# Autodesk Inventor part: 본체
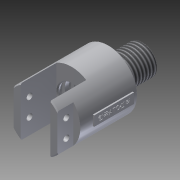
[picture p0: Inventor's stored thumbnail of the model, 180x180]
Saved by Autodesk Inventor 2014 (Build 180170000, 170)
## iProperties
Created: 2019-02
Part Number: 본체
Material: 알루미늄 6061
Document SubType Name: Modeling
Designer: OA55
Density: 2.71 g/cm^3
Appearance: 알루미늄 - 평지
Mass: 347.887 g
Surface Area: 290.046 cm^2
Volume: 128.372 cm^3
Author: OA55
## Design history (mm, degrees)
sketch "스케치1"
  geometry: C1 r 29 at (0, 0); 1 further point
  constraints: 1 centre point, 1 coincident
  dimensions: "d0" = 58 diameter of C1
extrude "돌출1" new body sketch "스케치1" stored distance "d1" = 74; taper "d2" = 0 deg
sketch "스케치2"
  geometry: L1 (29, -37)-(-29, -37) reference; L2 (-29, -37)-(-29, 37) reference; L3 (-29, 37)-(29, 37) reference; L4 (29, 37)-(29, -37) reference; L5 (15, 37)-(-15, 37); L6 (-15, 37)-(-15, 1); L7 (-15, 1)-(15, 1); L8 (15, 1)-(15, 37); L9 (22, 21)-(22, 37); L10 (0, 37)-(0, 0); L11 (22, 21)-(31.08, 21); L12 (31.08, 21)-(31.08, 37); L13 (31.08, 37)-(22, 37); L14 (-22, 21)-(-31.08, 21); L15 (-31.08, 21)-(-31.08, 37); L16 (-31.08, 37)-(-22, 37); L17 (-22, 21)-(-22, 37)
  constraints: 26 end point, 4 symmetric about line, 3 parallel, 2 perpendicular, 2 point on line, 1 collinear, 1 horizontal, 1 midpoint
  dimensions: "d6" = 36 distance of L7.end L5.start; "d7" = 30 distance of L6.end L7.end; "d8" = 15 distance from line of L10.end L8; "d10" = 22 distance between parallel lines of L10 L9; "d11" = 16 distance of L9.start L9.end; "d12" = 60.07958 distance between parallel lines of L2 L12
extrude "돌출2" cut sketch "스케치2" stored distance "d13" = 74; taper "d14" = 0 deg
sketch "스케치3"
  geometry: L1 (0, 0)-(0, 37.789) reference; L2 (16, 0)-(0, 0) reference; L3 (16, 37.789)-(16, 0) reference; L4 (73.898, 18.894)-(0, 18.894); C1 r 3 at (9, 27.894); C2 r 3 at (9, 9.894); 1 further point
  constraints: 2 centre point, 2 end point, 1 midpoint, 1 parallel, 1 symmetric about line, 1 other
  dimensions: "d15" = 6 diameter of C1; "d16" = 18 distance of C2.centre C1.centre; "d17" = 9 distance from line of L1 C1.centre; "d18" = 57.89803 distance from line of L4.start L3
extrude "돌출3" cut sketch "스케치3" distance "d19" = 50; taper "d20" = 0 deg
chamfer "모따기1" distance "d21" = 1; stored, may be unused: second distance "d22" = 2, angle "d23" = 45 deg
sketch "스케치4"
  geometry: C1 r 29 at (0, 0) reference; C2 r 13 at (0, 0); C3 r 15 at (0, 0)
  constraints: 2 centre point, 2 coincident
  dimensions: "d24" = 26 diameter of C2; "d25" = 30 diameter of C3
extrude "돌출7" join sketch "스케치4" distance "d43" = 5; taper "d44" = 0 deg
sketch "스케치7"
  geometry: C1 r 13 at (0, 0) reference; C2 r 15 at (0, 0)
  constraints: 1 centre point, 1 coincident
  dimensions: "d45" = 30 diameter of C2
extrude "돌출8" join sketch "스케치7" distance "d46" = 29; taper "d47" = 0 deg
feature "스레드2" dims "d48" = 10, "d49" = 0
sketch "스케치8"
  geometry: C1 r 15 at (0, 0) reference; C2 r 4 at (0, 0); 1 further point
  constraints: 2 coincident, 1 centre point
  dimensions: "d50" = 8 diameter of C2
hole "구멍2" sketch "스케치8" diameter "d51" = 11.835; stored, may be unused: countersink angle "d55" = 90 deg, drill point angle "d57" = 118 deg; dims "d52" = 18, "d53" = 4, "d54" = 2, "d56" = 22
extrude "돌출9" cut sketch "스케치8" stored distance "d58" = 31; taper "d59" = 0 deg
sketch "스케치9"
  geometry: L1 (0, 1.049)-(14, 1.049); L2 (14, -25.951)-(0, -25.951); L3 (0, -25.951)-(0, 1.049); L4 (0, 1.049)-(0, -25.951); L5 (0, -25.951)-(16, -25.951); L6 (16, -25.951)-(16, -18.951); L7 (16, -18.951)-(0, -18.951); L8 (17, -1.601)-(0, -1.601); L9 (17, -6.301)-(0, -6.301); L10 (20.309, -3.951)-(0, -3.951); L11 (20.309, -12.951)-(0, -12.951); L12 (17, -15.301)-(0, -15.301); L13 (17, -10.601)-(0, -10.601); L14 (17, -15.301)-(17, -10.601); L15 (17, -6.301)-(17, -1.601); L16 (14, 1.049)-(14, -1.601); L17 (14, -6.301)-(14, -10.601); L18 (14, -15.301)-(14, -18.951); 1 further point
  constraints: 36 end point, 11 parallel, 9 point on line, 7 perpendicular, 4 collinear, 1 horizontal
  dimensions: "d60" = 14 distance of L2.start L2.end; "d61" = 27 distance of L1.end L2.start; "d62" = 27 distance of L1.start L2.end (derived); "d63" = 16 distance of L2.end L5.end; "d64" = 7 distance of L5.end L6.end; "d67" = 4.7 distance between parallel lines of L9 L8; "d68" = 2.35 distance between parallel lines of L10 L9; "d69" = 9 distance between parallel lines of L11 L10; "d70" = 4.7 distance between parallel lines of L13 L12; "d71" = 2.35 distance between parallel lines of L12 L11; "d73" = 5 distance between parallel lines of L10 L1; "d74" = 3.65 distance between parallel lines of L12 L7; "d86" = 17 distance between parallel lines of L3 L14; "d105" = 20.30931 distance of L10.end L10.start; "d106" = 20.30931 distance of L11.start L11.end; "d107" = 17 distance from line of point (0, 0) L15; "d108" = 3.95062 distance from line of point (0, 0) L10; "d109" = 3.30931 distance from line of L11.start L15; "d110" = 17 distance from line of L9.end L15; "d113" = 0 distance between parallel lines of L14 L15; "d114" = 17 distance from line of L13.end L15; "d115" = 17 distance from line of L12.end L15
revolve "회전1" sketch "스케치9" stored, may be unused: angle "d116" = 90 deg
chamfer "모따기3" distance "d120" = 1; stored, may be unused: second distance "d121" = 2, angle "d122" = 45 deg
node "작업 평면1"
sketch "스케치10"
  geometry: L1 (5, 8)-(-5, 8); L2 (-5, 8)-(-5, -32); L3 (-5, -32)-(5, -32); L4 (5, -32)-(5, 8); L5 (-29, -37)-(29, -37) reference; 1 further point
  constraints: 8 end point, 2 parallel, 1 horizontal, 1 perpendicular
  dimensions: "d124" = 10 distance of L3.end L2.end; "d125" = 40 distance of L2.end L1.end; "d126" = 5 distance between parallel lines of L3 L5; "d127" = 5 distance from line of L4 point (0, 0)
extrude "돌출10" join sketch "스케치10" stored distance "d128" = 31; taper "d129" = 0 deg
sketch "스케치11"
  geometry: L1 (-8, 5)-(-8, -5) reference; L2 (-8, -5)-(32, -5) reference; 2 further points
  constraints: 1 other
  dimensions: "d130" = 20 distance from line of L1 point (12, 0); "d131" = 5 distance from line of L2 point (12, 0)
feature "엠보싱1" sketch "스케치11" dims "d132" = 0.5, "d133" = 0
chamfer "모따기4" distance "d134" = 1; stored, may be unused: second distance "d135" = 2, angle "d136" = 45 deg
chamfer "모따기5" distance "d137" = 1; stored, may be unused: second distance "d138" = 2, angle "d139" = 45 deg
fillet "모깎기1" dims "d140" = 0.8
node "솔리드1"
node "절단 모서리 투영1"
